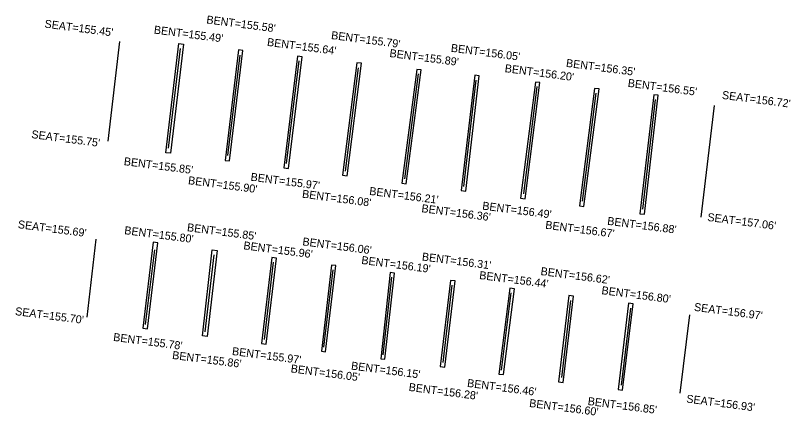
# Model space of a CAD drawing. Extents: x 2107167 to 2121551, y 865392 to 868477.
# Drawn here: x 2121163.2 to 2121550.6, y 867609.9 to 867809.8 of the extents above; entities that cross this region are included whole.
import ezdxf

# ---------------------------------------------------------------- set-up
doc = ezdxf.new("R2010")
doc.units = 0
for name, color, linetype in [('RD_EX_Bridge', 7, 'Continuous'), ('RD_EX_Bridge_txCode', 7, 'Continuous'), ('RD_EX_Conc', 7, 'Continuous')]:
    doc.layers.add(name, color=color, linetype=linetype)

msp = doc.modelspace()

# ---------------------------------------------------------------- linework, layer by layer
at = {"layer": 'RD_EX_Bridge'}
for p, q in [((2121215.24, 867796.86), (2121209.41, 867747.01)), ((2121239.64, 867743.44), (2121245.66, 867793.32)), ((2121269.36, 867739.87), (2121275.44, 867790.06)), ((2121298.7, 867735.85), (2121304.95, 867787.09)), ((2121328.09, 867732), (2121334.69, 867783.67)), ((2121357.8, 867728.23), (2121364.62, 867780.63)), ((2121387.36, 867724.43), (2121393.51, 867777.43)), ((2121423.84, 867774.27), (2121417.08, 867720.74)), ((2121446.59, 867717.02), (2121453.46, 867770.92)), ((2121476.75, 867712.94), (2121483.16, 867767.88)), ((2121506.03, 867708.97), (2121512.69, 867764.81)), ((2121203.26, 867698.11), (2121198.81, 867659.1)), ((2121228.22, 867655.43), (2121232.9, 867692.78)), ((2121257.95, 867651.66), (2121262.52, 867690.26)), ((2121287.58, 867647.92), (2121292.19, 867686.55)), ((2121317.35, 867644.11), (2121322.05, 867682.66)), ((2121346.97, 867640.23), (2121351.38, 867678.96)), ((2121376.91, 867636.45), (2121381.53, 867675.07)), ((2121406.22, 867632.57), (2121410.99, 867671.21)), ((2121440.72, 867667.46), (2121436.12, 867628.89)), ((2121470.59, 867663.59), (2121465.89, 867625.01)), ((2121500.16, 867660.14), (2121495.35, 867621.01))]:
    msp.add_line(p, q, dxfattribs=at)
at = {"layer": 'RD_EX_Conc'}
for points in [[(2121238.25, 867741.22), (2121244.89, 867795.75), (2121247.22, 867795.46), (2121240.58, 867740.93)], [(2121274.62, 867792.62), (2121267.95, 867737.41), (2121270.13, 867737.14), (2121276.81, 867792.35)], [(2121304.1, 867789.42), (2121297.29, 867733.63), (2121299.61, 867733.35), (2121306.41, 867789.14)], [(2121333.76, 867786.23), (2121326.59, 867729.95), (2121328.93, 867729.65), (2121336.1, 867785.93)], [(2121363.8, 867782.87), (2121356.29, 867726.04), (2121358.53, 867725.74), (2121366.04, 867782.57)], [(2121392.76, 867779.94), (2121385.94, 867722.3), (2121388.23, 867722.02), (2121395.05, 867779.67)], [(2121423.06, 867776.54), (2121415.66, 867718.54), (2121417.92, 867718.25), (2121425.32, 867776.25)], [(2121452.66, 867773.38), (2121445.11, 867714.68), (2121447.38, 867714.39), (2121454.93, 867773.09)], [(2121482.22, 867770.24), (2121475.35, 867710.77), (2121477.59, 867710.51), (2121484.46, 867769.98)], [(2121232.01, 867696.51), (2121226.87, 867653.5), (2121229.13, 867653.23), (2121234.27, 867696.24)], [(2121256.59, 867649.65), (2121261.44, 867692.63), (2121263.92, 867692.35), (2121259.07, 867649.37)], [(2121291.32, 867688.86), (2121286.17, 867645.84), (2121288.43, 867645.57), (2121293.58, 867688.59)], [(2121321.22, 867685.05), (2121316.08, 867642.01), (2121318.14, 867641.77), (2121323.29, 867684.8)], [(2121350.54, 867681.3), (2121345.75, 867638.22), (2121347.86, 867637.98), (2121352.65, 867681.06)], [(2121380.71, 867677.43), (2121375.54, 867634.39), (2121377.78, 867634.12), (2121382.94, 867677.16)], [(2121410.32, 867673.56), (2121404.82, 867630.63), (2121407.07, 867630.34), (2121412.57, 867673.27)], [(2121439.86, 867669.84), (2121434.64, 867626.7), (2121436.9, 867626.42), (2121442.12, 867669.56)], [(2121469.68, 867666.02), (2121464.39, 867622.92), (2121466.7, 867622.64), (2121471.99, 867665.74)]]:
    msp.add_lwpolyline(points, close=True, dxfattribs=at)

# ---------------------------------------------------------------- texts
at = {"layer": 'RD_EX_Bridge_txCode'}
for s, p in [("BENT=155.58'", (2121258.44, 867805.89)), ("SEAT=155.45'", (2121177.53, 867803.78)), ("BENT=155.49'", (2121232.18, 867800.83)), ("BENT=155.79'", (2121320.79, 867798.08)), ("BENT=155.64'", (2121288.77, 867794.67)), ("BENT=156.05'", (2121380.65, 867791.72)), ("BENT=155.89'", (2121349.98, 867789.11)), ("BENT=156.35'", (2121438.23, 867784.17)), ("BENT=156.20'", (2121407.59, 867781.55)), ("BENT=156.55'", (2121469.11, 867774.19)), ("SEAT=156.72'", (2121516.19, 867768.2)), ("SEAT=155.75'", (2121170.94, 867748.59)), ("BENT=155.85'", (2121217.14, 867735.08)), ("BENT=155.90'", (2121249.28, 867725.56)), ("BENT=155.97'", (2121280.53, 867727.27)), ("BENT=156.21'", (2121339.87, 867720.2)), ("BENT=156.08'", (2121306.26, 867718.79)), ("BENT=156.49'", (2121396.38, 867712.85)), ("BENT=156.36'", (2121365.96, 867711.56)), ("BENT=156.88'", (2121458.84, 867705.27)), ("SEAT=157.06'", (2121508.91, 867707.18)), ("SEAT=155.69'", (2121164.18, 867703.57)), ("BENT=155.80'", (2121217.39, 867700.59)), ("BENT=155.85'", (2121248.76, 867702.07)), ("BENT=156.67'", (2121427.86, 867703.28)), ("BENT=155.96'", (2121276.95, 867693.01)), ("BENT=156.06'", (2121306.45, 867694.98)), ("BENT=156.19'", (2121335.92, 867685.69)), ("BENT=156.31'", (2121366.19, 867687.44)), ("BENT=156.44'", (2121394.85, 867678.16)), ("BENT=156.62'", (2121425.51, 867680.14)), ("BENT=156.80'", (2121455.97, 867670.59)), ("SEAT=156.97'", (2121502.22, 867662.26)), ("SEAT=155.70'", (2121162.8, 867660.14)), ("BENT=155.78'", (2121211.85, 867647.23)), ("BENT=155.97'", (2121271.25, 867640.18)), ("BENT=155.86'", (2121241.33, 867638.22)), ("BENT=156.05'", (2121300.59, 867631.51)), ("BENT=156.15'", (2121330.77, 867632.91)), ("BENT=156.46'", (2121388.79, 867624.25)), ("BENT=156.28'", (2121359.58, 867622.25)), ("BENT=156.85'", (2121449.08, 867615.21)), ("SEAT=156.93'", (2121498.38, 867616.42)), ("BENT=156.60'", (2121419.82, 867614.22))]:
    msp.add_text(s, height=4, rotation=352.5747, dxfattribs=at).set_placement(p)

doc.saveas('drawing.dxf')
